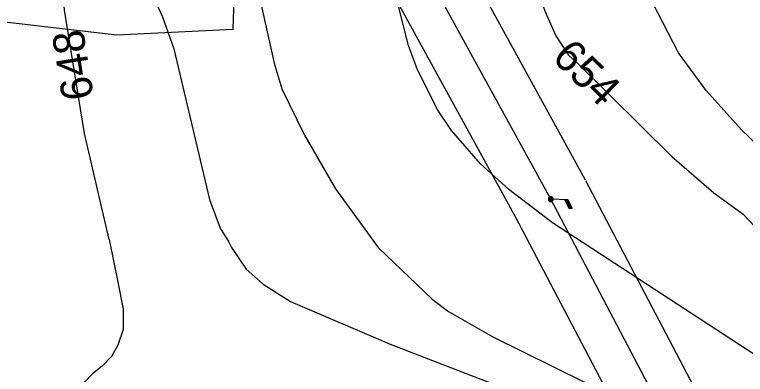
# Model space of a CAD drawing. Extents: x -709418 to -703832, y -1161719 to -1157826.
# Drawn here: x -706792.9 to -706607.7, y -1160678.1 to -1160586.9 of the extents above; entities that cross this region are included whole.
import ezdxf

# ---------------------------------------------------------------- set-up
doc = ezdxf.new("R2010")
doc.units = 0
for name, color, linetype in [('120_vrstevnice hlavní', 7, 'Continuous'), ('121_vrstevnice hlavní_popis', 7, 'Continuous'), ('122_vrstevnice základní', 7, 'Continuous'), ('124_vrstevnice doplňková', 7, 'Continuous'), ('301_polní cesta_stav', 7, 'Continuous'), ('705_el VN nadzemní_E.ON', 7, 'Continuous'), ('735_OP sítí TI', 7, 'Continuous')]:
    doc.layers.add(name, color=color, linetype=linetype)

# ---------------------------------------------------------------- blocks, each defined once
blk = doc.blocks.new('Elektro - Implicitní$0$VN4601')
for points in [[(1.23, 0), (1.22, 0.13), (1.2, 0.26), (1.17, 0.38), (1.12, 0.5), (1.06, 0.61), (0.99, 0.72), (0.91, 0.82), (0.82, 0.91), (0.72, 0.99), (0.61, 1.06), (0.5, 1.12), (0.38, 1.17), (0.26, 1.2), (0.13, 1.22), (0, 1.23), (-0.13, 1.22), (-0.26, 1.2), (-0.38, 1.17), (-0.5, 1.12), (-0.61, 1.06), (-0.72, 0.99), (-0.82, 0.91), (-0.91, 0.82), (-0.99, 0.72), (-1.06, 0.61), (-1.12, 0.5), (-1.17, 0.38), (-1.2, 0.26), (-1.22, 0.13), (-1.23, 0), (-1.22, -0.13), (-1.2, -0.26), (-1.17, -0.38), (-1.12, -0.5), (-1.06, -0.61), (-0.99, -0.72), (-0.91, -0.82), (-0.82, -0.91), (-0.72, -0.99), (-0.61, -1.06), (-0.5, -1.12), (-0.38, -1.17), (-0.26, -1.2), (-0.13, -1.22), (0, -1.23), (0.13, -1.22), (0.26, -1.2), (0.38, -1.17), (0.5, -1.12), (0.61, -1.06), (0.72, -0.99), (0.82, -0.91), (0.91, -0.82), (0.99, -0.72), (1.06, -0.61), (1.12, -0.5), (1.17, -0.38), (1.2, -0.26), (1.22, -0.13), (1.23, 0)], [(0.92, 0), (0.92, 0.1), (0.9, 0.19), (0.88, 0.28), (0.84, 0.37), (0.8, 0.46), (0.75, 0.54), (0.68, 0.62), (0.62, 0.68), (0.54, 0.74), (0.46, 0.8), (0.37, 0.84), (0.28, 0.88), (0.19, 0.9), (0.1, 0.92), (0, 0.92), (-0.1, 0.92), (-0.19, 0.9), (-0.28, 0.88), (-0.37, 0.84), (-0.46, 0.8), (-0.54, 0.74), (-0.62, 0.68), (-0.68, 0.62), (-0.75, 0.54), (-0.8, 0.46), (-0.84, 0.37), (-0.88, 0.28), (-0.9, 0.19), (-0.92, 0.1), (-0.92, 0), (-0.92, -0.1), (-0.9, -0.19), (-0.88, -0.29), (-0.84, -0.38), (-0.8, -0.46), (-0.75, -0.54), (-0.68, -0.62), (-0.62, -0.69), (-0.54, -0.75), (-0.46, -0.8), (-0.37, -0.84), (-0.28, -0.88), (-0.19, -0.9), (-0.1, -0.92), (0, -0.92), (0.1, -0.92), (0.19, -0.9), (0.28, -0.88), (0.37, -0.84), (0.46, -0.8), (0.54, -0.75), (0.62, -0.69), (0.68, -0.62), (0.75, -0.54), (0.8, -0.46), (0.84, -0.38), (0.88, -0.29), (0.9, -0.19), (0.92, -0.1), (0.92, 0)], [(0.61, 0), (0.61, 0.06), (0.6, 0.13), (0.58, 0.19), (0.56, 0.25), (0.53, 0.31), (0.5, 0.36), (0.46, 0.41), (0.41, 0.46), (0.36, 0.5), (0.31, 0.53), (0.25, 0.56), (0.19, 0.58), (0.13, 0.6), (0.06, 0.61), (0, 0.61), (-0.06, 0.61), (-0.13, 0.6), (-0.19, 0.58), (-0.25, 0.56), (-0.31, 0.53), (-0.36, 0.5), (-0.41, 0.46), (-0.46, 0.41), (-0.5, 0.36), (-0.53, 0.31), (-0.56, 0.25), (-0.58, 0.19), (-0.6, 0.13), (-0.61, 0.06), (-0.61, 0), (-0.61, -0.07), (-0.6, -0.13), (-0.58, -0.19), (-0.56, -0.25), (-0.53, -0.31), (-0.5, -0.36), (-0.46, -0.41), (-0.41, -0.46), (-0.36, -0.5), (-0.31, -0.53), (-0.25, -0.56), (-0.19, -0.58), (-0.13, -0.6), (-0.06, -0.61), (0, -0.61), (0.06, -0.61), (0.13, -0.6), (0.19, -0.58), (0.25, -0.56), (0.31, -0.53), (0.36, -0.5), (0.41, -0.46), (0.46, -0.41), (0.5, -0.36), (0.53, -0.31), (0.56, -0.25), (0.58, -0.19), (0.6, -0.13), (0.61, -0.06), (0.61, 0)], [(0.31, 0), (0.31, 0.03), (0.3, 0.06), (0.29, 0.09), (0.28, 0.12), (0.27, 0.15), (0.25, 0.18), (0.23, 0.21), (0.21, 0.23), (0.18, 0.25), (0.15, 0.27), (0.12, 0.28), (0.09, 0.29), (0.06, 0.3), (0.03, 0.31), (0, 0.31), (-0.03, 0.31), (-0.06, 0.3), (-0.09, 0.29), (-0.12, 0.28), (-0.15, 0.27), (-0.18, 0.25), (-0.21, 0.23), (-0.23, 0.21), (-0.25, 0.18), (-0.27, 0.15), (-0.28, 0.12), (-0.29, 0.09), (-0.3, 0.06), (-0.31, 0.03), (-0.31, 0), (-0.31, -0.03), (-0.3, -0.06), (-0.29, -0.1), (-0.28, -0.13), (-0.27, -0.15), (-0.25, -0.18), (-0.23, -0.21), (-0.21, -0.23), (-0.18, -0.25), (-0.15, -0.27), (-0.12, -0.28), (-0.09, -0.29), (-0.06, -0.3), (-0.03, -0.31), (0, -0.31), (0.03, -0.31), (0.06, -0.3), (0.09, -0.29), (0.12, -0.28), (0.15, -0.27), (0.18, -0.25), (0.21, -0.23), (0.23, -0.21), (0.25, -0.18), (0.27, -0.15), (0.28, -0.13), (0.29, -0.1), (0.3, -0.06), (0.31, -0.03), (0.31, 0)]]:
    blk.add_lwpolyline(points)
blk = doc.blocks.new('Elektro - Implicitní$0$VN0011')
for p, q in [((2.13, 3.73), (4.59, 3.73)), ((2.13, 3.72), (4.59, 3.72)), ((1.71, 3), (4.14, 3)), ((1.72, 3.02), (4.15, 3.02)), ((1.73, 3.04), (4.16, 3.04)), ((1.74, 3.06), (4.17, 3.06)), ((1.76, 3.08), (4.19, 3.08)), ((1.77, 3.1), (4.2, 3.1)), ((1.78, 3.12), (4.21, 3.12)), ((1.79, 3.14), (4.22, 3.14)), ((1.8, 3.16), (4.24, 3.16)), ((1.81, 3.18), (4.25, 3.18)), ((1.83, 3.2), (4.26, 3.2)), ((1.84, 3.22), (4.27, 3.22)), ((1.85, 3.24), (4.29, 3.24)), ((1.86, 3.26), (4.3, 3.26)), ((1.87, 3.28), (4.31, 3.28)), ((1.88, 3.3), (4.32, 3.3)), ((1.9, 3.32), (4.34, 3.32)), ((1.91, 3.34), (4.35, 3.34)), ((1.92, 3.36), (4.36, 3.36)), ((1.93, 3.38), (4.37, 3.38)), ((1.94, 3.4), (4.39, 3.4)), ((1.95, 3.42), (4.4, 3.42)), ((1.96, 3.44), (4.41, 3.44)), ((1.98, 3.46), (4.42, 3.46)), ((1.99, 3.48), (4.44, 3.48)), ((2, 3.5), (4.45, 3.5)), ((2.01, 3.52), (4.46, 3.52)), ((2.02, 3.54), (4.47, 3.54)), ((2.03, 3.56), (4.49, 3.56)), ((2.05, 3.58), (4.5, 3.58)), ((2.06, 3.6), (4.51, 3.6)), ((2.07, 3.62), (4.52, 3.62)), ((2.08, 3.64), (4.54, 3.64)), ((2.09, 3.66), (4.55, 3.66)), ((2.1, 3.68), (4.56, 3.68)), ((2.11, 3.7), (4.57, 3.7))]:
    blk.add_line(p, q)
for points in [[(2.13, 3.73), (0, 0)], [(4.59, 3.73), (2.13, 3.73), (1.7, 2.99), (4.13, 2.99), (4.59, 3.73)]]:
    blk.add_lwpolyline(points)

msp = doc.modelspace()

# ---------------------------------------------------------------- linework, layer by layer
at = {"layer": '120_vrstevnice hlavní'}
msp.add_lwpolyline([(-706726.99, -1160465.29), (-706728.97, -1160480.63), (-706732.53, -1160494.31), (-706736.1, -1160507.99), (-706737.38, -1160517.11), (-706737.66, -1160526.23), (-706736.67, -1160539.91), (-706732.25, -1160576.39), (-706727.12, -1160599.19), (-706725.16, -1160605.69), (-706719.42, -1160617.43), (-706711.59, -1160631.11), (-706700.76, -1160645.93), (-706687.08, -1160659.04), (-706682.95, -1160662.17), (-706671.69, -1160668.58), (-706640.77, -1160683.83), (-706620.39, -1160694.8), (-706577.64, -1160723.87)], dxfattribs=at)
at = {"layer": '122_vrstevnice základní'}
for points in [[(-706578.5, -1160645.07), (-706608.71, -1160616.15), (-706617.68, -1160606.17), (-706624.67, -1160596.62), (-706635.21, -1160576.1), (-706641.77, -1160557.87), (-706643.6, -1160551.76), (-706644.9, -1160544.19), (-706646.18, -1160525.95), (-706649.74, -1160500.87), (-706656.3, -1160478.07), (-706659.01, -1160464.39), (-706662.14, -1160441.59), (-706663.28, -1160427.91), (-706663.28, -1160421.07), (-706662.43, -1160411.95), (-706661.15, -1160405.54)], [(-706605.29, -1160673.14), (-706656.59, -1160639.66), (-706667.7, -1160631.25), (-706674.82, -1160624.7), (-706682.23, -1160616.29), (-706685.65, -1160611.16), (-706690.78, -1160600.9), (-706693.11, -1160594.78), (-706695.91, -1160583.8), (-706697.77, -1160573.54), (-706698.67, -1160565.05), (-706698.62, -1160555.87), (-706694.63, -1160507.99), (-706694.77, -1160498.87), (-706696.77, -1160469.23), (-706696.62, -1160460.11), (-706695.48, -1160448.72), (-706694.2, -1160441.88), (-706691.07, -1160431.47), (-706691.13, -1160418.59)], [(-706674.72, -1160417.84), (-706676.39, -1160430.19), (-706677.39, -1160445.86), (-706677.39, -1160467.81), (-706675.82, -1160486.62), (-706672.69, -1160508.56), (-706670.83, -1160521.1), (-706668.98, -1160539.91), (-706665.56, -1160561.85), (-706661.86, -1160577.53), (-706658.15, -1160586.93), (-706655.74, -1160592.27), (-706652.51, -1160597.16), (-706650.17, -1160599.33), (-706626.38, -1160622.84), (-706615.69, -1160632.1), (-706608.28, -1160637.52), (-706586.87, -1160660.09)], [(-706768.98, -1160643.9), (-706775.22, -1160617.06), (-706780.29, -1160585.76), (-706780.87, -1160578.09), (-706782.5, -1160562.47), (-706783.06, -1160548.1), (-706782.97, -1160523.12), (-706782.07, -1160513), (-706778.45, -1160499.11), (-706774.65, -1160489.12), (-706771.22, -1160481.47), (-706763.7, -1160463.96), (-706758.89, -1160460.02), (-706745.97, -1160459.43)], [(-706768.98, -1160643.9), (-706766.73, -1160654.76), (-706765.45, -1160661.6), (-706765.45, -1160666.73), (-706766.73, -1160670.72), (-706768.38, -1160673.53), (-706770.72, -1160675.99), (-706773.22, -1160677.94)], [(-706776.61, -1160705.09), (-706781.54, -1160699.03), (-706782.29, -1160694.13), (-706781.02, -1160688.16), (-706779.69, -1160684.83), (-706777.25, -1160682.16), (-706773.22, -1160677.94)]]:
    msp.add_lwpolyline(points, dxfattribs=at)
for points in [[(-706768.98, -1160643.9), (-706768.98, -1160643.9)], [(-706773.22, -1160677.94), (-706773.22, -1160677.94)]]:
    msp.add_open_spline(points, degree=1, dxfattribs=at)
at = {"layer": '124_vrstevnice doplňková'}
msp.add_lwpolyline([(-706760.55, -1160576.33), (-706755.47, -1160587.45), (-706752.53, -1160595.61), (-706743.51, -1160633.81), (-706740.81, -1160641.03), (-706738.68, -1160644.45), (-706737.98, -1160645.94), (-706734.25, -1160651.4), (-706729.97, -1160655.19), (-706722.99, -1160659.61), (-706697.77, -1160670.44), (-706668.84, -1160681.55), (-706654.88, -1160688.82), (-706648.89, -1160693.38), (-706640.91, -1160700.65), (-706635.21, -1160707.34), (-706629.94, -1160716.18)], dxfattribs=at)
at = {"layer": '301_polní cesta_stav'}
msp.add_lwpolyline([(-706993.15, -1160565.27), (-706965.02, -1160556.35), (-706942.71, -1160558.75), (-706861.06, -1160581.04), (-706767.05, -1160592.01), (-706737.54, -1160590.64), (-706736.73, -1160564.91), (-706748.65, -1160520.22), (-706748.65, -1160496.39), (-706691.02, -1160433.83)], dxfattribs=at)
at = {"layer": '705_el VN nadzemní_E.ON'}
for points in [[(-706657.04, -1160633.68), (-706687.59, -1160577.9), (-706687.63, -1160577.77), (-706742.25, -1160475.95), (-706787.13, -1160391.57), (-706827.37, -1160316.03), (-706880.73, -1160218.11)], [(-706126.79, -1160947.26), (-706166.94, -1160904.58), (-706239.08, -1160827.82), (-706352.93, -1160805.53), (-706485.08, -1160779.84), (-706590.79, -1160759.31), (-706626.96, -1160690.96), (-706657.04, -1160633.68)]]:
    msp.add_lwpolyline(points, dxfattribs=at)
at = {"layer": '735_OP sítí TI'}
for points in [[(-706648.27, -1160628.88), (-706678.38, -1160573.89), (-706678.41, -1160573.81), (-706733.43, -1160471.24), (-706778.3, -1160386.87), (-706818.57, -1160311.29), (-706870.8, -1160215.44)], [(-706665.81, -1160638.48), (-706696.8, -1160581.91), (-706696.85, -1160581.74), (-706751.07, -1160480.66), (-706795.96, -1160396.27), (-706836.17, -1160320.77), (-706885.08, -1160231.02)], [(-706119.51, -1160940.41), (-706159.66, -1160897.73), (-706234, -1160818.62), (-706351.01, -1160795.71), (-706483.17, -1160770.02), (-706584.19, -1160750.4), (-706618.11, -1160686.3), (-706648.19, -1160629.03)], [(-706134.08, -1160954.11), (-706174.22, -1160911.43), (-706244.16, -1160837.01), (-706354.84, -1160815.34), (-706486.99, -1160789.66), (-706597.39, -1160768.21), (-706635.81, -1160695.62), (-706665.89, -1160638.33)]]:
    msp.add_lwpolyline(points, dxfattribs=at)

# ---------------------------------------------------------------- block references
at = {"layer": '705_el VN nadzemní_E.ON', "xscale": 0.5, "yscale": 0.5, "rotation": -62.07375556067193}
msp.add_blockref('Elektro - Implicitní$0$VN4601', (-706657.04, -1160633.68), dxfattribs=at)
at = {"layer": '705_el VN nadzemní_E.ON', "rotation": -62.07375556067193}
msp.add_blockref('Elektro - Implicitní$0$VN0011', (-706657.04, -1160633.68), dxfattribs=at)

# ---------------------------------------------------------------- texts
at = {"layer": '121_vrstevnice hlavní_popis'}
for s, rotation, p in [('648', 99.0936, (-706772.82, -1160607.93)), ('654', 315.1876, (-706657, -1160598.1))]:
    msp.add_text(s, height=8, rotation=rotation, dxfattribs=at).set_placement(p)

doc.saveas('drawing.dxf')
